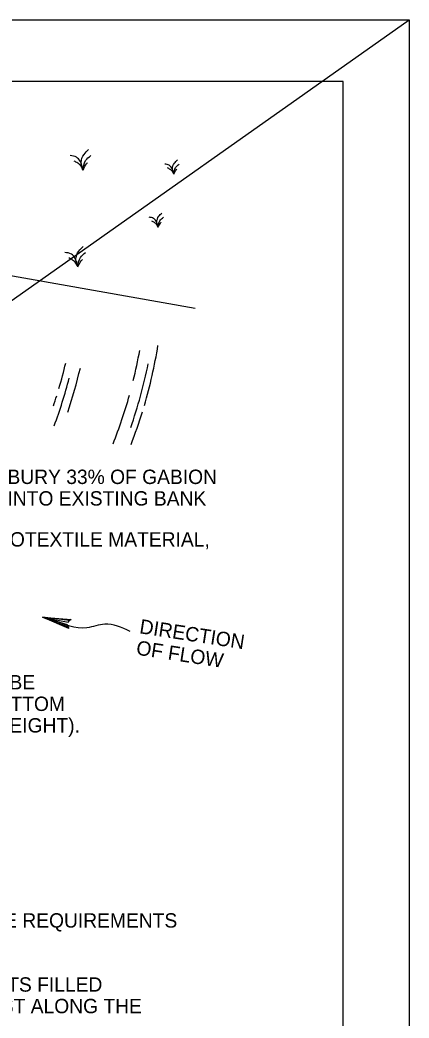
# Model space of a CAD drawing. Extents: x 3 to 3592, y -602 to 1171.
# Drawn here: x 3434.2 to 3528.9, y -250.9 to -7.8 of the extents above; entities that cross this region are included whole.
import ezdxf

# ---------------------------------------------------------------- set-up
doc = ezdxf.new("R2010")
doc.units = 0
for name, color, linetype in [('1', 7, 'Continuous'), ('2', 7, 'Continuous'), ('3', 7, 'Continuous')]:
    doc.layers.add(name, color=color, linetype=linetype)

msp = doc.modelspace()

# ---------------------------------------------------------------- linework, layer by layer
at = {"layer": '1'}
msp.add_line((2687.88, -601.81), (3528.88, -7.81), dxfattribs=at)
msp.add_lwpolyline([(2687.88, -7.81), (3528.88, -7.81), (3528.88, -601.81), (2687.88, -601.81)], close=True, dxfattribs=at)
msp.add_lwpolyline([(3512.88, -586.81), (3512.88, -22.81), (2726.88, -22.81), (2726.88, -586.81), (3512.88, -586.81), (3512.88, -560.45), (3312.88, -560.45), (3312.88, -495.77), (3512.88, -495.77), (3512.88, -466.81), (3312.88, -466.81), (3312.88, -586.81), (3391.68, -586.81), (3391.68, -560.45), (3391.68, -586.81), (3468.68, -586.81), (3468.68, -560.45), (3468.68, -572.77), (3512.88, -572.77)], dxfattribs=at)
at = {"layer": '2'}
msp.add_line((3415.52, -67.17), (3476.86, -78.01), dxfattribs=at)
msp.add_lwpolyline([(3445.89, -155.65), (3445.76, -155.13), (3439.74, -153.31), (3445.89, -155.65), (3446.14, -156), (3439.74, -153.31), (3445.91, -154.49), (3446.24, -154.09), (3439.74, -153.31), (3446.66, -153.87), (3446.24, -154.09)], dxfattribs=at)
for centre, start, end in [((3351.86, -68.58), 343.6194, 350.9409), ((3347.8, -67.57), 346.1712, 349.8399), ((3331.06, -64.52), 343.6544, 346.7741), ((3350.34, -68.33), 340.7219, 348.5764), ((3334.61, -65.79), 341.3488, 346.8024), ((3332.58, -65.54), 339.503, 345.4208), ((3331.06, -64.52), 341.4673, 342.7556), ((3347.8, -67.57), 338.2809, 344.3678), ((3351.86, -68.58), 338.7186, 342.8369)]:
    msp.add_arc(centre, 117.4, start, end, dxfattribs=at)
for points in [[(3449.56, -44.38), (3448.87, -42.21), (3447.99, -41.26), (3446.44, -40.86)], [(3449.56, -44.38), (3449.11, -42.5), (3449.81, -40.54), (3450.88, -39.4)], [(3449.56, -44.38), (3450.2, -42.07), (3451.45, -40.86)], [(3449.56, -44.38), (3449.11, -43.46), (3448.3, -42.69), (3447.38, -42.17)], [(3449.56, -44.38), (3450.4, -42.87), (3450.69, -42.55)], [(3471.62, -45.4), (3471.14, -43.88), (3470.52, -43.21), (3469.44, -42.93)], [(3471.62, -45.4), (3471.31, -44.08), (3471.8, -42.71), (3472.54, -41.91)], [(3471.62, -45.4), (3472.07, -43.78), (3472.95, -42.93)], [(3471.62, -45.4), (3471.31, -44.75), (3470.74, -44.21), (3470.1, -43.85)], [(3471.62, -45.4), (3472.21, -44.34), (3472.41, -44.11)], [(3467.82, -58.33), (3467.34, -56.81), (3466.72, -56.14), (3465.64, -55.86)], [(3467.82, -58.33), (3467.51, -57.01), (3467.99, -55.64), (3468.74, -54.84)], [(3467.82, -58.33), (3468.27, -56.71), (3469.14, -55.86)], [(3467.82, -58.33), (3467.51, -57.69), (3466.94, -57.15), (3466.29, -56.78)], [(3467.82, -58.33), (3468.41, -57.27), (3468.61, -57.05)], [(3448.29, -67.97), (3447.84, -66.08), (3448.54, -64.12), (3449.61, -62.99)], [(3448.29, -67.97), (3447.6, -65.8), (3446.72, -64.84), (3445.17, -64.44)], [(3448.29, -67.97), (3448.93, -65.65), (3450.18, -64.44)], [(3448.29, -67.97), (3447.85, -67.05), (3447.03, -66.28), (3446.11, -65.76)], [(3448.29, -67.97), (3449.13, -66.46), (3449.42, -66.13)], [(3461, -156.75), (3454.86, -154.97), (3450.5, -155.85), (3442.16, -153.94)]]:
    msp.add_spline(points, degree=3, dxfattribs=at)

# ---------------------------------------------------------------- texts
at = {"layer": '3'}
for s, p in [('BURY 33% OF GABION', (3431.18, -120.84)), ('INTO EXISTING BANK', (3431.18, -126.09)), ('CLASS 2, TYPE B GEOTEXTILE MATERIAL,', (3385.21, -136.07)), ('/2 MAX (GABIONS SHALL BE', (3374.7, -170.87)), ('KEYED INTO STREAM BOTTOM', (3374.7, -176.12)), ('UP TO 50% OF GABION HEIGHT).', (3374.7, -181.37)), ('PROVIDE MATERIALS AND CONSTRUCTION MEETING THE REQUIREMENTS', (3301.13, -228.89)), ('TYPE A GABIONS SHALL CONSIST OF WIRE-MESH BASKETS FILLED', (3300.3, -244.49)), ('BY HAND PLACEMENT OF COARSE AGGREGATE, AT LEAST ALONG THE', (3300.3, -249.74))]:
    msp.add_text(s, height=3.5, dxfattribs=at).set_placement(p)
for s, p in [('DIRECTION', (3463.14, -157.18)), ('OF FLOW', (3462.34, -162.37))]:
    msp.add_text(s, height=3.5, rotation=351.2538, dxfattribs=at).set_placement(p)

doc.saveas('drawing.dxf')
